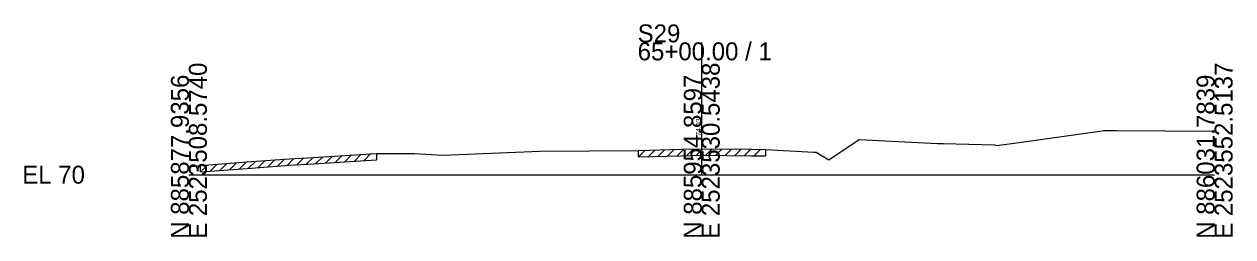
# Model space of a CAD drawing. Extents: x -26 to 163, y -10 to 4024.
# Drawn here: x -25.7 to 162.8, y 3490.3 to 3523.5 of the extents above; entities that cross this region are included whole.
import ezdxf

# ---------------------------------------------------------------- set-up
doc = ezdxf.new("R2010")
doc.units = 0
for name, color, linetype in [('RD_GPK_XS_Cell', 7, 'Continuous'), ('RD_XS_ExGround', 7, 'Continuous'), ('RD_XS_ExPaveRet', 7, 'Continuous'), ('RD_XS_TX_Elev_EX', 7, 'Continuous')]:
    doc.layers.add(name, color=color, linetype=linetype)

msp = doc.modelspace()

# ---------------------------------------------------------------- linework, layer by layer
at = {"layer": 'RD_GPK_XS_Cell'}
for p, q in [((80, 3500), (80, 3520.64)), ((0, 3500), (80, 3500)), ((80, 3500), (160, 3500))]:
    msp.add_line(p, q, dxfattribs=at)
at = {"layer": 'RD_XS_ExGround'}
for p, q in [((128.35, 3504.88), (142.09, 3506.79)), ((142.09, 3506.79), (142.68, 3506.88)), ((142.68, 3506.88), (144.67, 3506.87)), ((144.67, 3506.87), (160, 3506.79)), ((99.84, 3502.34), (104.55, 3505.48)), ((104.55, 3505.48), (116.78, 3504.86)), ((116.78, 3504.86), (117.68, 3504.88)), ((117.68, 3504.88), (125.64, 3504.65)), ((125.98, 3504.57), (128.35, 3504.88)), ((19.43, 3502.7), (29.28, 3503.33)), ((29.28, 3503.33), (31.88, 3503.33)), ((31.88, 3503.33), (35.14, 3503.33)), ((35.14, 3503.33), (39.6, 3503.05)), ((39.6, 3503.05), (54.72, 3503.66)), ((54.72, 3503.66), (62.48, 3503.74)), ((62.48, 3503.74), (70.15, 3503.77)), ((70.15, 3503.77), (76.79, 3503.96)), ((76.79, 3503.96), (80.06, 3504.03)), ((80.06, 3504.03), (87.72, 3503.96)), ((87.72, 3503.96), (89.95, 3503.92)), ((89.95, 3503.92), (97.47, 3503.52)), ((97.47, 3503.52), (97.87, 3503.5)), ((97.87, 3503.5), (98.77, 3502.96)), ((98.77, 3502.96), (99.84, 3502.34)), ((125.64, 3504.65), (125.98, 3504.57)), ((0, 3501.2), (1.82, 3501.43)), ((1.82, 3501.43), (9.1, 3501.98)), ((9.1, 3501.98), (15.63, 3502.46)), ((15.63, 3502.46), (19.43, 3502.7))]:
    msp.add_line(p, q, dxfattribs=at)
at = {"layer": 'RD_XS_ExPaveRet'}
for p, q in [((22.82, 3501.92), (23.89, 3502.99)), ((24.32, 3502.01), (25.39, 3503.08)), ((25.82, 3502.11), (26.89, 3503.18)), ((27.32, 3502.21), (28.39, 3503.28)), ((29.28, 3503.33), (29.28, 3502.33)), ((70.15, 3502.77), (71.18, 3503.8)), ((70.15, 3502.77), (70.15, 3503.77)), ((70.15, 3502.77), (76.79, 3502.96)), ((71.65, 3502.81), (72.68, 3503.84)), ((73.15, 3502.86), (74.18, 3503.89)), ((74.65, 3502.9), (75.68, 3503.93)), ((76.15, 3502.94), (77.18, 3503.97)), ((76.79, 3502.96), (80.06, 3503.03)), ((77.65, 3502.98), (78.68, 3504)), ((79.15, 3503.01), (80.17, 3504.03)), ((80.06, 3503.03), (87.72, 3502.96)), ((80.65, 3503.03), (81.64, 3504.02)), ((82.15, 3503.01), (83.14, 3504)), ((83.65, 3503), (84.64, 3503.99)), ((85.15, 3502.98), (86.14, 3503.97)), ((86.65, 3502.97), (87.64, 3503.96)), ((87.72, 3502.96), (89.95, 3502.92)), ((88.15, 3502.95), (89.14, 3503.93)), ((89.95, 3503.92), (89.95, 3502.92)), ((1.82, 3500.43), (2.91, 3501.51)), ((1.82, 3500.43), (1.82, 3501.43)), ((3.32, 3500.54), (4.41, 3501.62)), ((4.82, 3500.66), (5.91, 3501.74)), ((6.32, 3500.77), (7.41, 3501.85)), ((7.82, 3500.88), (8.91, 3501.97)), ((9.1, 3500.98), (15.63, 3501.46)), ((9.32, 3501), (10.4, 3502.08)), ((10.82, 3501.11), (11.9, 3502.19)), ((12.32, 3501.22), (13.4, 3502.3)), ((13.82, 3501.33), (14.9, 3502.41)), ((15.32, 3501.44), (16.39, 3502.51)), ((15.63, 3501.46), (19.43, 3501.7)), ((16.82, 3501.53), (17.89, 3502.6)), ((18.32, 3501.63), (19.39, 3502.7)), ((19.43, 3501.7), (29.28, 3502.33)), ((19.82, 3501.73), (20.89, 3502.8)), ((21.32, 3501.82), (22.39, 3502.89)), ((1.82, 3500.43), (9.1, 3500.98))]:
    msp.add_line(p, q, dxfattribs=at)

# ---------------------------------------------------------------- texts
at = {"layer": 'RD_GPK_XS_Cell'}
for s, p in [('S29', (70, 3520.64)), ('65+00.00 / 1', (70, 3517.84)), ('EL 70', (-26, 3498.6))]:
    msp.add_text(s, height=2.8, dxfattribs=at).set_placement(p)
for s, p in [('E 2523508.5740', (2.8, 3490)), ('E 2523530.5438', (82.8, 3490)), ('E 2523552.5137', (162.8, 3490)), ('N 885877.9356', (0, 3490)), ('N 885954.8597', (80, 3490)), ('N 886031.7839', (160, 3490))]:
    msp.add_text(s, height=2.8, rotation=90, dxfattribs=at).set_placement(p)
at = {"layer": 'RD_XS_TX_Elev_EX'}
msp.add_text('74.03', height=0.8, rotation=90, dxfattribs=at).set_placement((79.9, 3506.03))

doc.saveas('drawing.dxf')
